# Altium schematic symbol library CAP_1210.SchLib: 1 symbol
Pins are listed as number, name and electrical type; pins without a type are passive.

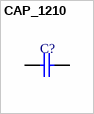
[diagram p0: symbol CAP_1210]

## CAP_1210
designator C?
footprint CAP_1210
pins: 1, 2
